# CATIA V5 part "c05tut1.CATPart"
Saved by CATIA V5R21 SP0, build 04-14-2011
Part number: Part1
Bounding box of the stored display mesh (mm): x -20 to 20, y -95 to 0, z 0 to 40
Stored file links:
  D:\CATIA V5R21 E-RESOURCES\CATIA-V5R21\catia-v5r21-prt\c05-catia-v5r20-prt\catia-v5r21-tut-01.CATPart
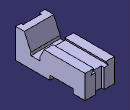
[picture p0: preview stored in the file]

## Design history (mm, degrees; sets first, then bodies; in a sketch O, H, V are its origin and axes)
Body1 (main body)
  Sketch1 on yz-plane, origin (0, 0, 0), H (0, 1, 0), V (0, 0, 1)
    line L1 (0, 0) -> (-16, 0)
    line L2 (-16, 0) -> (-16, 6)
    line L3 (-16, 6) -> (-48, 6)
    line L4 (-48, 6) -> (-48, 0)
    point P4 (-48, 0)
    line L5 (-48, 0) -> (-95, 0)
    line L6 (-95, 0) -> (-95, 40)
    line L7 (-95, 40) -> (-83, 40)
    line L8 (-83, 40) -> (-74, 20)
    line L9 (-74, 20) -> (-74, 16)
    line L10 (-74, 16) -> (-62, 16)
    line L11 (-62, 16) -> (-62, 20)
    point P11 (-62, 20)
    line L12 (-62, 20) -> (-56, 32)
    point P12 (-56, 32)
    line L13 (-56, 32) -> (0, 32)
    point P13 (0, 32)
    line L14 (0, 32) -> (0, 0)
    length L1 = 16
    length L3 = 32
    distance L14 L6 = 95
    length L2 = 6
    length L14 = 32
    length L9 = 4
    distance L5 L10 = 16
    length L7 = 12
    distance L11 P12 = 6
    length L10 = 12
    length L13 = 56
    distance P11 L13 = 12
    length L6 = 40
    horizontal: L1 H, L3 H, L5 H, L7 H, L10 H, L13 H
    vertical: L2 V, L4 V, L6 V, L9 V, L11 V, L14 V
    coincidence: P4 H, P13 V
  Pad1: profile Sketch1, direction (1, 0, 0), length 20, mirrored extent
  Sketch2 on face of Pad1 from Sketch1.L14, origin (0, 0, 0), H (-1, 0, 0), V (0, 0, 1)
    point P1 (-12, 26)
    line L1 (-12, 26) -> (12, 26)
    point P2 (12, 26)
    line L2 (12, 26) -> (8, 32)
    point P3 (8, 32)
    line L3 (8, 32) -> (-8, 32)
    point P4 (-8, 32)
    line L4 (-8, 32) -> (-12, 26)
    reference projected line E1 (20, 32) -> (-20, 32) from edge [face of Pad1 from Sketch1.L13 | face of Pad1 from Sketch1.L14]
    reference projected line E2 (20, 0) -> (20, 32) from edge [start face of Pad1 | face of Pad1 from Sketch1.L14]
    reference projected line E3 (-20, 0) -> (-20, 32) from edge [face of Pad1 from Sketch1.L14 | end face of Pad1]
    reference projected line E4 (-20, 0) -> (-20, 32) from edge [face of Pad1 from Sketch1.L14 | end face of Pad1]
    reference projected line E5 (20, 0) -> (20, 32) from edge [start face of Pad1 | face of Pad1 from Sketch1.L14]
    distance L1 L3 = 6
    distance P3 E2 = 12
    distance P4 E3 = 12
    distance P1 E4 = 8
    distance P2 E5 = 8
    horizontal: L1 H, L3 H
    coincidence: E1 L3
  Pocket1: profile Sketch2, direction (0, -1, 0), through (limit type 6)
  Sketch3 on face of Pad1 from Sketch1.L14, origin (0, 0, 0), H (-1, 0, 0), V (0, 0, 1)
    point P1 (6, 0)
    line L1 (6, 0) -> (-6, 0)
    line L2 (-6, 0) -> (-6, 26)
    line L3 (-6, 26) -> (6, 26)
    line L4 (6, 26) -> (6, 0)
    reference projected line E1 (-12, 26) -> (12, 26) from edge [face of Pad1 from Sketch1.L14 | face of Pocket1 from Sketch2.L1]
    length L1 = 12
    distance V L4 = 6
    coincidence: P1 H, E1 L3
    horizontal: L1 H, L3 H
    vertical: L2 V, L4 V
  Pocket2: profile Sketch3, direction (0, -1, 0), length 4
  Sketch4 on face of Pad1 from Sketch1.L7, origin (0, 0, 40), H (1, 0, 0), V (0, 1, 0)
    line L1 (-12.5, -95) -> (12.5, -95)
    line L2 (12.5, -95) -> (12.5, -92)
    line L3 (12.5, -92) -> (-12.5, -92)
    line L4 (-12.5, -92) -> (-12.5, -95)
    reference projected line E1 (-20, -95) -> (20, -95) from edge [face of Pad1 from Sketch1.L6 | face of Pad1 from Sketch1.L7]
    reference projected line E2 (-20, -83) -> (-20, -95) from edge [start face of Pad1 | face of Pad1 from Sketch1.L7]
    length L1 = 25
    length L4 = 3
    distance L4 E2 = 7.5
    horizontal: L1 H, L3 H
    vertical: L2 V, L4 V
    coincidence: E1 L1
  Pocket3: profile Sketch4, direction (0, 0, -1), through (limit type 3)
